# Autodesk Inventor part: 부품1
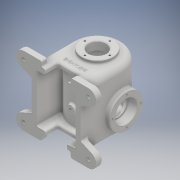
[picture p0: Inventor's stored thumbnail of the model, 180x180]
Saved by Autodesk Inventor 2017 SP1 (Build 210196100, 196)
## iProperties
Part Number: 부품1
Material: 일반
Document SubType Name: Modeling
Designer: MRC
Density: 1 g/cm^3
Appearance: 기본값
Author: MRC
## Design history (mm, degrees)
sketch "스케치1"
  geometry: C1 r 45 at (0, 0); 1 further point
  constraints: 1 centre point, 1 coincident
  dimensions: "d0" = 90 diameter of C1
extrude "돌출1" new body sketch "스케치1" stored distance "d1" = 108; taper "d2" = 0 deg
sketch "스케치2"
  geometry: L1 (-45, 0)-(45, 0); L2 (45, 0)-(45, -76); L3 (45, -76)-(-45, -76); L4 (-45, -76)-(-45, 0); 2 further points
  constraints: 8 end point, 2 parallel, 1 horizontal, 1 horizontal alignment, 1 perpendicular, 1 vertical, 1 other
  dimensions: "d3" = 90 distance of L2.end L3.end; "d4" = 76 distance of L1.end L2.end
extrude "돌출2" join sketch "스케치2" stored distance "d5" = 108; taper "d6" = 0 deg
sketch "스케치3"
  geometry: L1 (0, -54)-(0, 54) reference; L2 (0, 54)-(0, -14); C1 r 31 at (0, -14); 1 further point
  constraints: 2 end point, 1 centre point, 1 coincident, 1 point on line
  dimensions: "d7" = 68 distance of L1.end L2.end; "d8" = 62 diameter of C1
extrude "돌출3" join sketch "스케치3" stored distance "d9" = 108; taper "d10" = 0 deg
node "작업 평면1"
sketch "스케치4"
  geometry: L1 (45, 54)-(-45, 54) reference; L2 (0, 54)-(0, -14); C1 r 7.5 at (0, -14); 1 further point
  constraints: 2 end point, 1 centre point, 1 coincident, 1 midpoint, 1 vertical
  dimensions: "d11" = 68 distance of L2.start L2.end; "d12" = 15 diameter of C1
extrude "돌출4" join sketch "스케치4" distance "d13" = 4; taper "d15" = 0 deg; dims "d14" = 4, "d16" = 0
sketch "스케치6"
  geometry: C1 r 17.5 at (0, 0); 1 further point
  constraints: 1 centre point
  dimensions: "d20" = 35 diameter of C1
extrude "돌출6" cut sketch "스케치6" stored distance "d21" = 6; taper "d22" = 0 deg
sketch "스케치7"
  geometry: C1 r 20 at (0, 0); 1 further point
  constraints: 1 centre point
  dimensions: "d23" = 40 diameter of C1
extrude "돌출7" cut sketch "스케치7" distance "d24" = 16; taper "d25" = 0 deg
sketch "스케치8"
  geometry: C1 r 20 at (0, 0); 1 further point
  constraints: 1 centre point
  dimensions: "d26" = 40 diameter of C1
extrude "돌출8" cut sketch "스케치8" distance "d27" = 16; taper "d28" = 0 deg
sketch "스케치9" dims "d29" = 52
  geometry: 6 further points
  constraints: 1 vertical alignment, 7 other
  dimensions: "d32" = 360 deg dimension on point (0, 0) point (0, 26) (derived)
hole "구멍1" sketch "스케치9" at (0, 26), (-26, 0), (0, -26), (26, 0) diameter "d34" = 3.242; stored, may be unused: countersink angle "d38" = 90 deg, drill point angle "d40" = 118 deg; dims "d35" = 8, "d36" = 4, "d37" = 2, "d39" = 10
sketch "스케치11"
  geometry: C1 r 28.5 at (0, 0); 1 further point
  constraints: 1 centre point, 1 coincident
  dimensions: "d44" = 57 diameter of C1
extrude "돌출10" join sketch "스케치11" distance "d45" = 6; taper "d46" = 0 deg
sketch "스케치12"
  geometry: C1 r 16.5 at (0, 0); 1 further point
  constraints: 1 centre point, 1 coincident
  dimensions: "d47" = 33 diameter of C1
extrude "돌출11" cut sketch "스케치12" distance "d48" = 15; taper "d49" = 0 deg
sketch "스케치13"
  geometry: C1 r 36 at (0, 0); 1 further point
  constraints: 1 centre point, 1 coincident
  dimensions: "d50" = 72 diameter of C1
extrude "돌출12" cut sketch "스케치13" distance "d51" = 90; taper "d52" = 0 deg
sketch "스케치14" dims "d53" = 46
  geometry: 6 further points
  constraints: 1 coincident, 1 vertical alignment, 7 other
  dimensions: "d56" = 360 deg dimension on point (0, 0) point (0, 23) (derived)
hole "구멍2" sketch "스케치14" at (0, 23), (-23, 0), (0, -23), (23, 0) diameter "d58" = 3.242; stored, may be unused: countersink angle "d62" = 90 deg, drill point angle "d64" = 118 deg; dims "d59" = 8, "d60" = 4, "d61" = 2, "d63" = 10
node "작업 평면2"
sketch "스케치15"
  geometry: L1 (-45, 0)-(-45, -76) reference; L2 (-45, 0)-(-45, -76); L3 (45, -76)-(-45, -76) reference; L4 (-45, -76)-(45, -76); L5 (45, 0)-(45, -76) reference; L6 (45, -76)-(45, 0); A1 r 45 centre (0, 0) between (-45, 0) and (45, 0); 1 further point
  constraints: 7 end point, 2 collinear, 2 point on circle, 1 centre point, 1 coincident, 1 horizontal
extrude "돌출13" cut sketch "스케치15" stored distance "d67" = 90; taper "d68" = 0 deg
node "작업 평면3"
sketch "스케치16"
  geometry: L1 (-45, -54)-(45, -54) reference; L2 (45, -54)-(45, 54) reference; L3 (-45, -54)-(45, -54); L4 (45, -54)-(45, 54); L5 (45, 54)-(-45, 54); L6 (-45, 54)-(-45, -54); L7 (-36, 45)-(36, 45); L8 (36, 45)-(36, -45); L9 (36, -45)-(-36, -45); L10 (-36, -45)-(-36, 45); 1 further point
  constraints: 16 end point, 4 parallel, 2 perpendicular, 1 horizontal, 1 point on line, 3 other
  dimensions: "d70" = 9 distance between parallel lines of L5 L7
extrude "돌출14" join sketch "스케치16" stored distance "d5" = 108; taper "d6" = 0 deg; stored distance "d71" = 90; taper "d72" = 0 deg
sketch "스케치17"
  geometry: L1 (-20, 0)-(20, 0) reference; C1 r 20 at (0, 0); 1 further point
  constraints: 1 centre point, 1 midpoint
  dimensions: "d73" = 40 diameter of C1
extrude "돌출15" cut sketch "스케치17" stored distance "d74" = 90; taper "d75" = 0 deg
sketch "스케치18"
  geometry: C1 r 20 at (0, 0); 1 further point
  constraints: 1 centre point
  dimensions: "d76" = 40 diameter of C1
extrude "돌출16" cut sketch "스케치18" stored distance "d77" = 90; taper "d78" = 0 deg
sketch "스케치19"
  geometry: L1 (0, 0)-(0, -76.109); L2 (0, -76.109)-(20, -76.109); L3 (20, -76.109)-(20, -53.109); L4 (20, -53.109)-(-20, -53.109); L5 (-20, -53.109)-(-20, -76.109); L6 (-20, -76.109)-(0, -76.109)
  constraints: 12 end point, 2 perpendicular, 1 horizontal, 1 point on line, 1 vertical
  dimensions: "d79" = 20 distance of L1.end L2.end; "d80" = 23 distance of L2.end L3.end; "d81" = 40 distance of L3.end L4.end; "d82" = 23 distance of L4.end L5.end
extrude "돌출17" cut sketch "스케치19" stored distance "d83" = 90; taper "d84" = 0 deg
sketch "스케치20"
  geometry: L1 (-45, 54)-(-45, -54) reference; L2 (-45, -54)-(-20, -54) reference; L3 (-36, 45)-(-36, -45) reference; L4 (-36, -45)-(-20, -45) reference; L5 (-60, -64)-(-27, -64); L6 (-27, -64)-(-27, -45); L7 (-36, -23.994)-(-45, -28); L8 (-45, -28)-(-65.693, -37.21); A1 r 14 centre (-60, -50) between (-65.693, -37.21) and (-60, -64); 1 further point
  constraints: 8 end point, 3 point on line, 3 tangent, 2 point on circle, 1 centre point, 1 horizontal, 1 perpendicular
  dimensions: "d87" = 14 radius of A1; "d88" = 50 vertical distance of point (0, 0) A1.centre; "d89" = 60 horizontal distance of point (0, 0) A1.centre; "d90" = 18 distance between parallel lines of L1 L6; "d91" = 36 distance from line of L7.end L5
extrude "돌출18" join sketch "스케치20" distance "d92" = 12; taper "d93" = 0 deg
sketch "스케치21"
  geometry: 2 further points
hole "구멍3" sketch "스케치21" at (0, 0) diameter "d94" = 5.188; stored, may be unused: countersink angle "d98" = 90 deg, drill point angle "d100" = 118 deg; dims "d95" = 12, "d96" = 4, "d97" = 2, "d99" = 16
fillet "모깎기1" dims "d101" = 0.3
chamfer "모따기1" distance "d102" = 1; stored, may be unused: second distance "d103" = 2, angle "d104" = 45 deg
fillet "모깎기2" dims "d105" = 3
sketch "스케치22"
  geometry: A1 r 14 centre (120, -14) between (125.693, -26.79) and (120, 0) reference; 2 further points
  constraints: 1 coincident
hole "구멍4" sketch "스케치22" at (120, -14) diameter "d106" = 6.6; stored, may be unused: countersink angle "d110" = 90 deg, drill point angle "d112" = 118 deg; dims "d107" = 12, "d108" = 18, "d109" = 2, "d111" = 12
fillet "모깎기3" dims "d113" = 3
fillet "모깎기4" dims "d114" = 12
fillet "모깎기5" dims "d115" = 3
fillet "모깎기6" dims "d116" = 3
fillet "모깎기7" dims "d117" = 3
fillet "모깎기8" dims "d118" = 3
fillet "모깎기9" dims "d119" = 3
fillet "모깎기10" dims "d120" = 3
fillet "모깎기11" dims "d121" = 3
sketch "스케치23"
  geometry: L1 (60, -76)-(30, -76) reference; 2 further points
  constraints: 1 vertical alignment, 1 other
  dimensions: "d122" = 35 distance from line of L1 point (0, -41)
feature "엠보싱1" sketch "스케치23" dims "d123" = 0.5, "d124" = 0
node "솔리드1"
mirror "미러1"
mirror "미러2"
mirror "미러3"
mirror "미러4"
mirror "미러5"
mirror "미러6"
other parameters: "d65" = -76, "d69" = -76
